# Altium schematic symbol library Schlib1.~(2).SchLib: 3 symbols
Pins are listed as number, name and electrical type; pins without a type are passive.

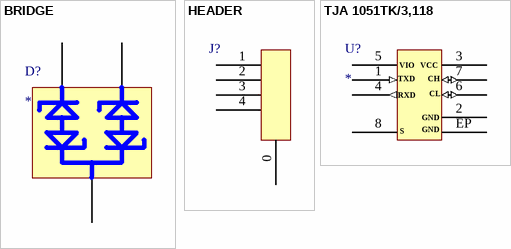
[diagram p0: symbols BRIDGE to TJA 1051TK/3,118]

## BRIDGE
designator D?
pins: 1, 2, 3

## HEADER
designator J?  (value not drawn)
pins: 0, 1, 2, 3, 4

## TJA 1051TK/3,118
designator U?
pins: 1 (in), 2, 3, 4 (out), 5, 6 (io), 7 (io), 8, EP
